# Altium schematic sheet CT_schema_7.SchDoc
size 278 x 170 mm
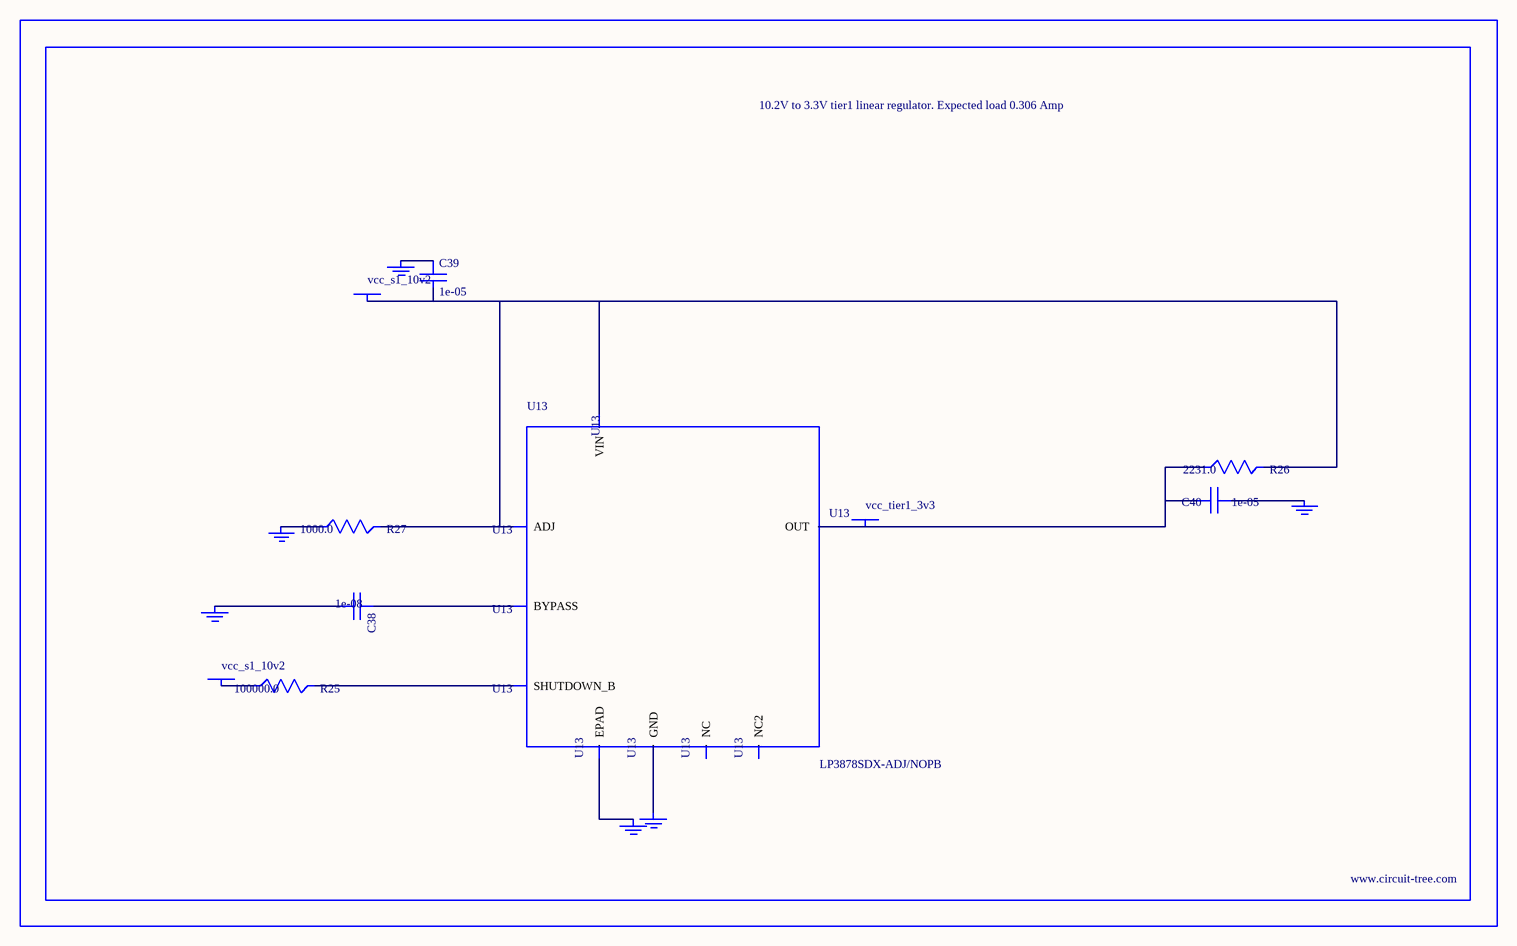
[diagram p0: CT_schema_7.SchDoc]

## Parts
BORDER6  (no value)
C38  1e-08  [C0402]
C39  1e-05  [C1206]
C40  1e-05  [C1210]
GND_INSTANCE_6_0  (no value)
GND_INSTANCE_6_1  (no value)
GND_INSTANCE_6_2  (no value)
GND_INSTANCE_6_3  (no value)
GND_INSTANCE_6_4  (no value)
GND_INSTANCE_6_5  (no value)
POWER_INSTANCE_6_0  vcc_s1_10v2
POWER_INSTANCE_6_1  vcc_s1_10v2
POWER_INSTANCE_6_2  vcc_tier1_3v3
R25  100000.0  [R0603]
R26  2231.0  [R0603]
R27  1000.0  [R0603]
U13  LP3878SDX-ADJ/NOPB  [WSON-8]

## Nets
NetC38_1: C38.1 U13.1(BYPASS)
NetC38_2: C38.2 GND_INSTANCE_6_0.0(GND)
NetC39_1: C39.1 GND_INSTANCE_6_1.0(GND)
NetC39_2: C39.2 POWER_INSTANCE_6_0.0(PWR) R26.2 R27.2 U13.4(VIN) U13.6(ADJ)
NetC40_1: C40.1 GND_INSTANCE_6_2.0(GND)
NetC40_2: C40.2 POWER_INSTANCE_6_2.0(PWR) R26.1 U13.5(OUT)
NetGND_INSTANCE_6_3_0: GND_INSTANCE_6_3.0(GND) R27.1
NetGND_INSTANCE_6_4_0: GND_INSTANCE_6_4.0(GND) U13.PAD(EPAD)
NetGND_INSTANCE_6_5_0: GND_INSTANCE_6_5.0(GND) U13.3(GND)
NetPOWER_INSTANCE_6_1_0: POWER_INSTANCE_6_1.0(PWR) R25.1
NetR25_2: R25.2 U13.8(SHUTDOWN_B)

Not connected (* = marked no-connect by the designer): U13 2(NC) 7(NC2)

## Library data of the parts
BORDER6 = BORDER_PAGE6
C38 = C0402C103K3RAC
C39 = C1206C106K3RACTU
C40 = GRM32DR61E106MA12L
GND_INSTANCE_6_0-GND_INSTANCE_6_5 = GND
POWER_INSTANCE_6_0-POWER_INSTANCE_6_2 = PWR
R25 = RC0603JR-07100KL
R26 = R26
R27 = RC0603JR-071KL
